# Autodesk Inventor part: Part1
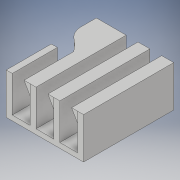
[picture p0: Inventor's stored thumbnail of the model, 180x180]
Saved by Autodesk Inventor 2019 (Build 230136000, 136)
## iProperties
Created: 2019-01
Part Number: Part1
Material: Generic
Document SubType Name: Modeling
Designer: Patel Family
Density: 1 g/cm^3
Appearance: Default
Author: Patel Family
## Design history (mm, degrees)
sketch "Sketch1"
  geometry: L1 (8.178, 9.531)-(8.178, -9.531); L2 (8.178, -9.531)-(-8.178, -9.531); L3 (-8.178, -9.531)-(-8.178, 9.531); L4 (-8.178, 9.531)-(8.178, 9.531); L5 (8.178, 9.531)-(-8.178, -9.531); L6 (8.178, -9.531)-(-8.178, 9.531); 1 further point
  constraints: 12 end point, 2 midpoint, 2 parallel, 1 perpendicular, 1 vertical
extrude "Extrusion1" new body sketch "Sketch1" distance "d0" = 1.0668; taper "d1" = 0 deg
sketch "Sketch2"
  geometry: L1 (8.178, 9.531)-(-8.178, 9.531) reference; L2 (-8.178, -9.531)-(8.178, -9.531) reference; L3 (-8.178, 9.531)-(-6.908, 9.531); L4 (-6.908, -9.531)-(-8.178, -9.531); L5 (-8.178, -9.531)-(-8.178, 9.531); L6 (8.178, -9.531)-(8.178, 9.531) reference; L7 (8.178, 9.531)-(6.908, 9.531); L8 (6.908, 9.531)-(6.908, -9.531); L9 (6.908, -9.531)-(8.178, -9.531); L10 (8.178, -9.531)-(8.178, 9.531); L11 (-6.908, 9.531)-(-3.149, 9.531); L12 (-3.149, 9.531)-(-1.879, 9.531); L13 (-1.879, 9.531)-(1.88, 9.531); L14 (1.88, 9.531)-(3.15, 9.531); L15 (3.15, 9.531)-(6.908, 9.531); L16 (-3.149, 9.531)-(-1.879, 9.531); L17 (-1.879, 9.531)-(-1.879, -9.531); L18 (-1.879, -9.531)-(-3.149, -9.531); L19 (-3.149, -9.531)-(-3.149, 9.531); L20 (1.88, 9.531)-(3.15, 9.531); L21 (3.15, 9.531)-(3.15, -9.531); L22 (3.15, -9.531)-(1.88, -9.531); L23 (1.88, -9.531)-(1.88, 9.531); L24 (-8.178, 9.531)-(-8.178, -9.531) reference; L25 (-6.908, -9.531)-(-8.178, -9.531); L26 (-8.178, -9.531)-(-8.178, 0); L27 (-8.178, 0)-(-6.908, 0); L28 (-6.908, 0)-(-6.908, -9.531); L29 (-1.879, 2.213)-(-8.178, 2.213); L30 (-8.178, 2.213)-(-8.178, 9.531); L31 (-8.178, 9.531)-(-1.879, 9.531); L32 (-1.879, 9.531)-(-1.879, 2.213); 1 further point
  constraints: 56 end point, 11 parallel, 9 point on line, 6 horizontal, 5 perpendicular, 1 collinear, 1 midpoint
  dimensions: "d2" = 1.27 distance of L4.start L4.end; "d3" = 1.27 distance of L9.end L8.end; "d4" = 13.81632 distance of L7.end L3.end (derived); "d5" = 3.7592 distance of L3.end L11.end; "d6" = 1.27 distance of L11.end L12.end; "d7" = 3.7592 distance of L12.end L13.end; "d8" = 1.27 distance of L13.end L14.end
extrude "Extrusion2" join sketch "Sketch2" distance "d9" = 7.62; taper "d10" = 0 deg
sketch "Sketch3"
  geometry: L1 (-6.908, 9.531)-(-6.908, -9.531) reference; L2 (-6.908, 9.531)-(-3.149, 9.531); L3 (1.88, 9.531)-(1.88, -9.531) reference; L4 (8.178, -9.531)-(-8.178, -9.531) reference; L5 (-3.149, 9.531)-(-1.879, 9.531); L6 (-1.879, 9.531)-(-1.879, -9.531); L7 (-1.879, -9.531)-(-3.149, -9.531); L8 (-3.149, -9.531)-(-3.149, 9.531); 1 further point
  constraints: 10 end point, 2 parallel, 2 perpendicular, 1 horizontal, 1 point on line
  dimensions: "d11" = 3.7592 distance of L1.start L2.end; "d12" = 1.27 distance of L6.end L7.end
extrude "Extrusion3" join sketch "Sketch3" distance "d13" = 7.62; taper "d14" = 0 deg
sketch "Sketch4"
  geometry: L1 (-3.149, 9.531)-(-3.149, -9.531) reference; L2 (-8.178, 9.531)-(-8.178, 0) reference; L3 (-3.149, 9.531)-(-8.178, 9.531); L4 (-8.178, 9.531)-(-8.178, 2.52); L5 (-8.178, 2.52)-(-3.149, 2.52); L6 (-3.149, 2.52)-(-3.149, 9.531); 1 further point
  constraints: 8 end point, 2 parallel, 1 horizontal, 1 perpendicular, 1 point on line
extrude "Extrusion4" join sketch "Sketch4" distance "d15" = 7.62; taper "d16" = 0 deg
fillet "Fillet1" dims "d17" = 3.81
sketch "Sketch5"
  geometry: L1 (-3.149, -9.531)-(-3.149, 2.52) reference; L2 (-3.149, -2.032)-(-3.149, 2.52); L3 (-4.368, 2.52)-(-3.149, 2.52) reference; L4 (-6.854, 3.443)-(-3.149, 2.52); A1 r 3.81 centre (-4.368, 6.33) between (-8.178, 6.33) and (-4.368, 2.52) reference; A2 r 9.206 centre (-12.117, -4.11) between (-3.149, -2.032) and (-6.854, 3.443); 1 further point
  constraints: 4 end point, 3 point on circle, 1 centre point, 1 collinear, 1 point on line
extrude "Extrusion5" join sketch "Sketch5" distance "d18" = 7.62; taper "d19" = 0 deg
sketch "Sketch6"
  geometry: L1 (8.178, 8.687)-(6.908, 8.687) reference; L2 (6.908, 8.687)-(5.639, 8.687); L3 (5.639, 8.687)-(6.908, 6.457); L4 (6.908, 1.067)-(6.908, 8.687) reference; L5 (6.908, 6.457)-(6.908, 8.687); L6 (1.899, 8.687)-(0.629, 8.687); L7 (0.629, 8.687)-(1.88, 6.457); L8 (1.88, 1.067)-(1.88, 8.687) reference; L9 (1.88, 6.457)-(1.88, 8.687); L10 (-3.149, 1.067)-(-3.149, 8.687) reference; L11 (-3.149, 8.687)-(-4.419, 8.687); L12 (-1.879, 8.687)-(-8.178, 8.687) reference; L13 (-4.419, 8.687)-(-3.149, 6.457); L14 (-3.149, 6.457)-(-3.149, 8.687); 1 further point
  constraints: 18 end point, 3 point on line, 2 collinear, 2 horizontal, 1 perpendicular
  dimensions: "d20" = 2.5654 distance of L2.end L3.end; "d21" = 1.27 distance of L6.start L6.end; "d22" = 1.27 distance of L10.end L11.end
extrude "Extrusion6" join sketch "Sketch6" distance "d23" = 9.525; taper "d25" = 0 deg; dims "d24" = 9.525, "d26" = 0
body "Solid1"
